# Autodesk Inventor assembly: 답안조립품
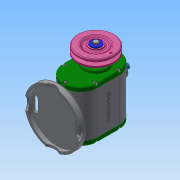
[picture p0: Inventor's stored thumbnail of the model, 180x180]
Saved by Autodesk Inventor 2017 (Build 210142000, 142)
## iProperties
Part Number: 답안조립품
Material: 일반
Document SubType Name: Assembly
Designer: user
Mass: 3121.24 g
Surface Area: 2356.27 cm^2
Volume: 792.061 cm^3
Density: 3.94066 g/cm^3
Author: user
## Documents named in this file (19)
- C:\Users\user\Desktop\611006V1008\답안조립품.iam
- C:\Users\user\Desktop\611006V1008\V-벨트풀리.ipt
- C:\Users\user\Desktop\611006V1008\가변스프링.ipt
- C:\Users\user\Desktop\611006V1008\뒤커버.ipt
- C:\Users\user\Desktop\611006V1008\멈춤나사 M3.ipt
- C:\Users\user\Desktop\611006V1008\메인축.ipt
- C:\Users\user\Desktop\611006V1008\베어링 608.ipt
- C:\Users\user\Desktop\611006V1008\베어링 6003.ipt
- C:\Users\user\Desktop\611006V1008\본체.ipt
- C:\Users\user\Desktop\611006V1008\볼트 M4.ipt
- C:\Users\user\Desktop\611006V1008\볼트 M6.ipt
- C:\Users\user\Desktop\611006V1008\부시.ipt
- C:\Users\user\Desktop\611006V1008\서브축.ipt
- C:\Users\user\Desktop\611006V1008\슬라이더.ipt
- C:\Users\user\Desktop\611006V1008\앞커버.ipt
- C:\Users\user\Desktop\611006V1008\오일실 8x22x7.ipt
- C:\Users\user\Desktop\611006V1008\오일실 17x32x8.ipt
- C:\Users\user\Desktop\611006V1008\와셔.ipt
- C:\Users\user\Desktop\611006V1008\키 5x5.ipt
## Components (2 placed, 2 different names)
1. V-벨트풀리:1 — 플러쉬:1, 각도:2
2. 가변스프링:1
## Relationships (2: Flush 1, Angle 1)
- 플러쉬:1 [Flush]: V-벨트풀리:1
- 각도:2 [Angle]: V-벨트풀리:1
